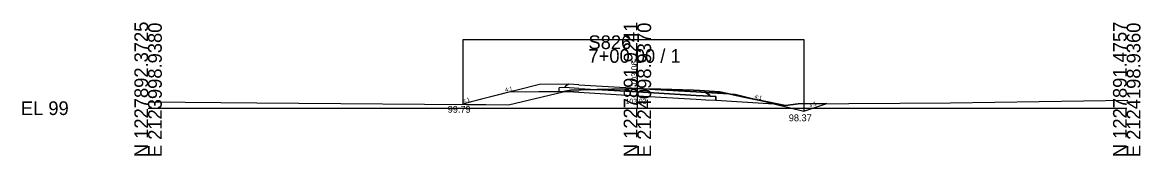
# Model space of a CAD drawing. Extents: x 2118382 to 2118616, y 1213030 to 1222057.
# Drawn here: x 2118381.9 to 2118610.4, y 1217530.1 to 1217557.3 of the extents above; entities that cross this region are included whole.
import ezdxf

# ---------------------------------------------------------------- set-up
doc = ezdxf.new("R2010")
doc.units = 0
for name, color, linetype in [('XS_CELL', 7, 'Continuous'), ('XS_M_DITCH', 7, 'Continuous'), ('XS_M_SHAPES_EARTHWORK', 7, 'Continuous'), ('XS_P_FINISHED_GRADE', 7, 'Continuous'), ('XS_P_FINISHED_GRADE_ELEV_TX', 7, 'Continuous'), ('XS_P_SUBGRADE_GRANULAR', 7, 'Continuous'), ('XS_P_SUBGRADE_PAVEMENT', 7, 'Continuous'), ('XS_P_TX_DCH', 7, 'Continuous'), ('XS_P_TX_FS_BS', 7, 'Continuous'), ('XS_X_GROUND', 7, 'Continuous'), ('XS_X_GROUND_TX', 7, 'Continuous')]:
    doc.layers.add(name, color=color, linetype=linetype)

msp = doc.modelspace()

# ---------------------------------------------------------------- linework, layer by layer
at = {"layer": 'XS_CELL'}
for p, q in [((2118507.6, 1217539.8), (2118507.6, 1217551.88)), ((2118407.6, 1217539.8), (2118507.6, 1217539.8)), ((2118507.6, 1217539.8), (2118607.6, 1217539.8))]:
    msp.add_line(p, q, dxfattribs=at)
at = {"layer": 'XS_M_DITCH'}
for p, q in [((2118471.98, 1217540.59), (2118471.98, 1217553.86)), ((2118471.98, 1217553.86), (2118541.6, 1217553.86)), ((2118541.6, 1217553.86), (2118541.6, 1217539.17))]:
    msp.add_line(p, q, dxfattribs=at)
at = {"layer": 'XS_M_SHAPES_EARTHWORK'}
for p, q in [((2118481.34, 1217543.06), (2118473.6, 1217541.13)), ((2118481.28, 1217540.52), (2118492.41, 1217543.15)), ((2118492.41, 1217543.15), (2118492.54, 1217543.18)), ((2118493.64, 1217543.45), (2118492.54, 1217543.18)), ((2118492.54, 1217543.18), (2118493.6, 1217543.19)), ((2118493.6, 1217543.19), (2118495.6, 1217543.08)), ((2118494.03, 1217543.47), (2118493.64, 1217543.45)), ((2118496.08, 1217543.52), (2118494.03, 1217543.47)), ((2118495.6, 1217543.08), (2118507.6, 1217542.36)), ((2118499.35, 1217543.6), (2118496.08, 1217543.52)), ((2118505.4, 1217543.76), (2118499.35, 1217543.6)), ((2118505.4, 1217543.76), (2118499.35, 1217543.6)), ((2118499.35, 1217543.6), (2118507.6, 1217543.11)), ((2118499.35, 1217543.6), (2118507.6, 1217543.11)), ((2118507.6, 1217543.11), (2118499.35, 1217543.6)), ((2118507.6, 1217543.82), (2118505.4, 1217543.76)), ((2118507.6, 1217543.82), (2118505.4, 1217543.76)), ((2118508.87, 1217543.79), (2118507.6, 1217543.82)), ((2118508.87, 1217543.79), (2118507.6, 1217543.82)), ((2118507.6, 1217543.11), (2118519.6, 1217542.4)), ((2118507.6, 1217543.11), (2118519.6, 1217542.4)), ((2118519.6, 1217542.4), (2118507.6, 1217543.11)), ((2118507.6, 1217542.36), (2118519.6, 1217541.65)), ((2118512.38, 1217543.69), (2118508.87, 1217543.79)), ((2118508.87, 1217543.79), (2118519.6, 1217543.15)), ((2118519.6, 1217543.15), (2118508.87, 1217543.79)), ((2118519.6, 1217543.15), (2118508.87, 1217543.79)), ((2118519.05, 1217543.5), (2118512.38, 1217543.69)), ((2118520.32, 1217543.39), (2118519.05, 1217543.5)), ((2118519.6, 1217543.15), (2118521.6, 1217543.03)), ((2118521.6, 1217543.03), (2118519.6, 1217543.15)), ((2118521.6, 1217543.03), (2118519.6, 1217543.15)), ((2118519.6, 1217542.4), (2118522.44, 1217542.23)), ((2118519.6, 1217542.4), (2118522.44, 1217542.23)), ((2118522.44, 1217542.23), (2118519.6, 1217542.4)), ((2118524.35, 1217543.11), (2118520.32, 1217543.39)), ((2118521.6, 1217543.03), (2118522.26, 1217542.53)), ((2118526.03, 1217542.77), (2118521.6, 1217543.03)), ((2118521.6, 1217543.03), (2118526.03, 1217542.77)), ((2118522.26, 1217542.53), (2118521.6, 1217543.03)), ((2118522.26, 1217542.53), (2118521.6, 1217543.03)), ((2118522.26, 1217542.53), (2118522.44, 1217542.23)), ((2118522.44, 1217542.23), (2118522.26, 1217542.53)), ((2118522.44, 1217542.23), (2118522.26, 1217542.53)), ((2118522.44, 1217542.23), (2118523.6, 1217542.16)), ((2118523.6, 1217542.16), (2118522.44, 1217542.23)), ((2118523.6, 1217542.16), (2118523.6, 1217541.41)), ((2118523.6, 1217541.41), (2118523.6, 1217542.16)), ((2118526.03, 1217542.77), (2118524.35, 1217543.11)), ((2118529.68, 1217542.02), (2118526.03, 1217542.77)), ((2118532.85, 1217541.36), (2118529.68, 1217542.02)), ((2118473.6, 1217541.13), (2118471.98, 1217540.59)), ((2118471.98, 1217540.59), (2118481.28, 1217540.52)), ((2118519.6, 1217541.65), (2118521.6, 1217541.53)), ((2118521.6, 1217541.53), (2118523.6, 1217541.41)), ((2118523.6, 1217541.41), (2118535.47, 1217540.71)), ((2118537.85, 1217540.33), (2118532.85, 1217541.36)), ((2118535.47, 1217540.71), (2118532.85, 1217541.36)), ((2118540.43, 1217540.7), (2118537.85, 1217540.33)), ((2118546.3, 1217540.74), (2118540.43, 1217540.7)), ((2118541.6, 1217539.17), (2118546.3, 1217540.74))]:
    msp.add_line(p, q, dxfattribs=at)
for points in [[(2118492.54, 1217543.18), (2118491.6, 1217543.17), (2118481.34, 1217543.06)], [(2118532.85, 1217541.36), (2118535.47, 1217540.71), (2118541.6, 1217539.17)]]:
    msp.add_lwpolyline(points, dxfattribs=at)
at = {"layer": 'XS_P_FINISHED_GRADE'}
for p, q in [((2118487.6, 1217544.63), (2118473.6, 1217541.13)), ((2118493.6, 1217544.69), (2118487.6, 1217544.63)), ((2118495.6, 1217544.58), (2118493.6, 1217544.69)), ((2118495.6, 1217544.58), (2118507.6, 1217543.86)), ((2118507.6, 1217543.86), (2118519.6, 1217543.15)), ((2118519.6, 1217543.15), (2118521.6, 1217543.03)), ((2118521.6, 1217543.03), (2118527.6, 1217542.67)), ((2118527.6, 1217542.67), (2118541.6, 1217539.17)), ((2118473.6, 1217541.13), (2118471.98, 1217540.59)), ((2118541.6, 1217539.17), (2118546.3, 1217540.74))]:
    msp.add_line(p, q, dxfattribs=at)
at = {"layer": 'XS_P_SUBGRADE_GRANULAR'}
for p, q in [((2118492.73, 1217544), (2118491.6, 1217543.98)), ((2118493.6, 1217543.19), (2118481.34, 1217543.06)), ((2118491.6, 1217543.17), (2118491.6, 1217543.98)), ((2118495.6, 1217543.08), (2118493.6, 1217543.19)), ((2118495.6, 1217543.08), (2118507.6, 1217542.36)), ((2118507.6, 1217542.36), (2118519.6, 1217541.65)), ((2118522.44, 1217542.23), (2118523.6, 1217542.16)), ((2118523.6, 1217541.41), (2118523.6, 1217542.16)), ((2118519.6, 1217541.65), (2118521.6, 1217541.53)), ((2118521.6, 1217541.53), (2118523.6, 1217541.41)), ((2118523.6, 1217541.41), (2118535.47, 1217540.71))]:
    msp.add_line(p, q, dxfattribs=at)
at = {"layer": 'XS_P_SUBGRADE_PAVEMENT'}
for p, q in [((2118492.89, 1217544.28), (2118492.73, 1217544)), ((2118495.6, 1217543.83), (2118492.73, 1217544)), ((2118493.6, 1217544.69), (2118492.89, 1217544.28)), ((2118495.6, 1217543.83), (2118507.6, 1217543.11)), ((2118507.6, 1217543.11), (2118519.6, 1217542.4)), ((2118519.6, 1217542.4), (2118522.44, 1217542.23)), ((2118521.6, 1217543.03), (2118522.26, 1217542.53)), ((2118522.26, 1217542.53), (2118522.44, 1217542.23))]:
    msp.add_line(p, q, dxfattribs=at)
at = {"layer": 'XS_X_GROUND'}
for p, q in [((2118481.28, 1217540.52), (2118492.41, 1217543.15)), ((2118492.41, 1217543.15), (2118493.64, 1217543.45)), ((2118493.64, 1217543.45), (2118494.03, 1217543.47)), ((2118494.03, 1217543.47), (2118496.08, 1217543.52)), ((2118496.08, 1217543.52), (2118505.4, 1217543.76)), ((2118505.4, 1217543.76), (2118507.6, 1217543.82)), ((2118507.6, 1217543.82), (2118512.38, 1217543.69)), ((2118512.38, 1217543.69), (2118519.05, 1217543.5)), ((2118519.05, 1217543.5), (2118520.32, 1217543.39)), ((2118520.32, 1217543.39), (2118524.35, 1217543.11)), ((2118524.35, 1217543.11), (2118529.68, 1217542.02)), ((2118529.68, 1217542.02), (2118537.85, 1217540.33)), ((2118407.81, 1217541.1), (2118429.82, 1217540.92)), ((2118429.82, 1217540.92), (2118481.28, 1217540.52)), ((2118537.85, 1217540.33), (2118540.43, 1217540.7)), ((2118540.43, 1217540.7), (2118571.56, 1217540.92)), ((2118571.56, 1217540.92), (2118607.81, 1217541.45))]:
    msp.add_line(p, q, dxfattribs=at)

# ---------------------------------------------------------------- texts
at = {"layer": 'XS_CELL'}
for s, p in [('N 1227892.3725', (2118407.6, 1217529.8)), ('E 2123998.9380', (2118410.4, 1217529.8)), ('N 1227891.9241', (2118507.6, 1217529.8)), ('E 2124098.9370', (2118510.4, 1217529.8)), ('N 1227891.4757', (2118607.6, 1217529.8)), ('E 2124198.9360', (2118610.4, 1217529.8))]:
    msp.add_text(s, height=2.8, rotation=90, dxfattribs=at).set_placement(p)
for s, p in [('S826', (2118497.6, 1217551.88)), ('7+00.00 / 1', (2118497.6, 1217549.08)), ('EL 99', (2118381.6, 1217538.4))]:
    msp.add_text(s, height=2.8, dxfattribs=at).set_placement(p)
at = {"layer": 'XS_P_FINISHED_GRADE_ELEV_TX'}
msp.add_text(' 103.06', height=1.25, rotation=90, dxfattribs=at).set_placement((2118507.6, 1217543.86))
at = {"layer": 'XS_P_TX_DCH'}
for s, p in [('99.79', (2118468.83, 1217538.87)), ('98.37', (2118538.54, 1217537.13))]:
    msp.add_text(s, height=1.4, dxfattribs=at).set_placement(p)
at = {"layer": 'XS_P_TX_FS_BS'}
for s, rotation, p in [('4:1', 14.0362, (2118480.64, 1217543.12)), ('3:1', 18.4349, (2118471.99, 1217540.79)), ('4:1', 345.9638, (2118531.48, 1217541.86)), ('3:1', 18.404, (2118542.81, 1217539.96))]:
    msp.add_text(s, height=0.8, rotation=rotation, dxfattribs=at).set_placement(p)
at = {"layer": 'XS_X_GROUND_TX'}
msp.add_text('103.02', height=1, dxfattribs=at).set_placement((2118505.21, 1217540.73))

doc.saveas('drawing.dxf')
